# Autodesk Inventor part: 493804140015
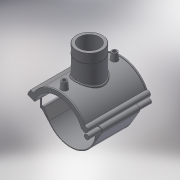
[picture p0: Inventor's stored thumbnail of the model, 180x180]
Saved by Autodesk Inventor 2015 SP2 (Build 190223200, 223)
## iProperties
Created: 2017-07
Part Number: 493804140015
Material: Generic
Description: PLASSON TRANSITION SADDLE 140-1.1/2"
Document SubType Name: Modeling
Designer: KIM
Density: 1 g/cm^3
Appearance: Default
Author: KIM
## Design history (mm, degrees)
derived "493804.ipt"
feature "Solid1::493804.ipt"
tag "TaggingFeature1"
body "Solid1"
other parameters: "B_" = 175, "H_" = 53, "L_" = 118, "d_t" = 6, "G_" = 44.845, "d148" = 2.1, "d160" = 2.1, "d169" = 2.1, "d192" = 4.2, "d1" = 161, "d2" = 175, "d3" = 35, "d4" = 118, "d5" = 0, "d6" = 0.1, "d8" = 0, "d19" = 6, "d20" = 6, "d21" = 70.8, "d23" = 0, "d24" = 35.4, "d26" = 0, "d27" = 3, "d28" = 3, "d29" = 3, "d30" = 46.66667, "d31" = 6, "d32" = 0, "d33" = 0, "d34" = 0.6, "d40" = 83.72, "d41" = 62.783, "d43" = 0, "d45" = 0, "d47" = 133.5, "d48" = 58.2985, "d50" = 0, "d70" = 15, "d72" = 0, "d73" = 6, "d75" = 5, "d76" = 0, "d77" = 7, "d79" = 15, "d80" = 47.2, "d82" = 5 deg, "d84" = 4, "d85" = 14, "d86" = 0, "d87" = 3, "d88" = 0, "d89" = 1, "d90" = 1, "d91" = 94.4, "d92" = 0, "d93" = 0.5, "d94" = 73.68421, "d96" = 164.22, "d97" = 2.36, "d98" = 0, "d102" = 1.34535, "d103" = 44.845, "d104" = 31.8, "d105" = 0, "d106" = 35.876, "d108" = 0, "d109" = -17.66667, "d111" = 0.5, "d112" = 0.5, "d113" = 0, "d114" = 0.5, "d117" = 0.44845, "d120" = 140 deg, "d121" = 24.228, "d122" = 20 deg, "d123" = 322, "d124" = 96.6, "d126" = 0, "d143" = 144.2, "d145" = 16.15385, "d149" = 2.1, "d150" = 17.76923, "d153" = 118, "d154" = 0, "d156" = 80.5, "d157" = 160 deg, "d159" = 4.2, "d161" = 2.1, "d162" = 70.8, "d163" = 0, "d167" = 14, "d168" = 78.53659, "d170" = 2.1, "d172" = 0, "d173" = 1, "d176" = 20 deg, "d177" = 9.8, "d178" = 21, "d180" = 0, "d183" = 8.4, "d184" = 7.84, "d185" = 38.35, "d186" = 38.35, "d187" = 80.5, "d188" = 6.3, "d189" = 9.8, "d190" = 0, "d191" = 96.6, "d193" = 4.2, "d194" = 2.95, "d195" = 90 deg, "d197" = 0, "d199" = 0
